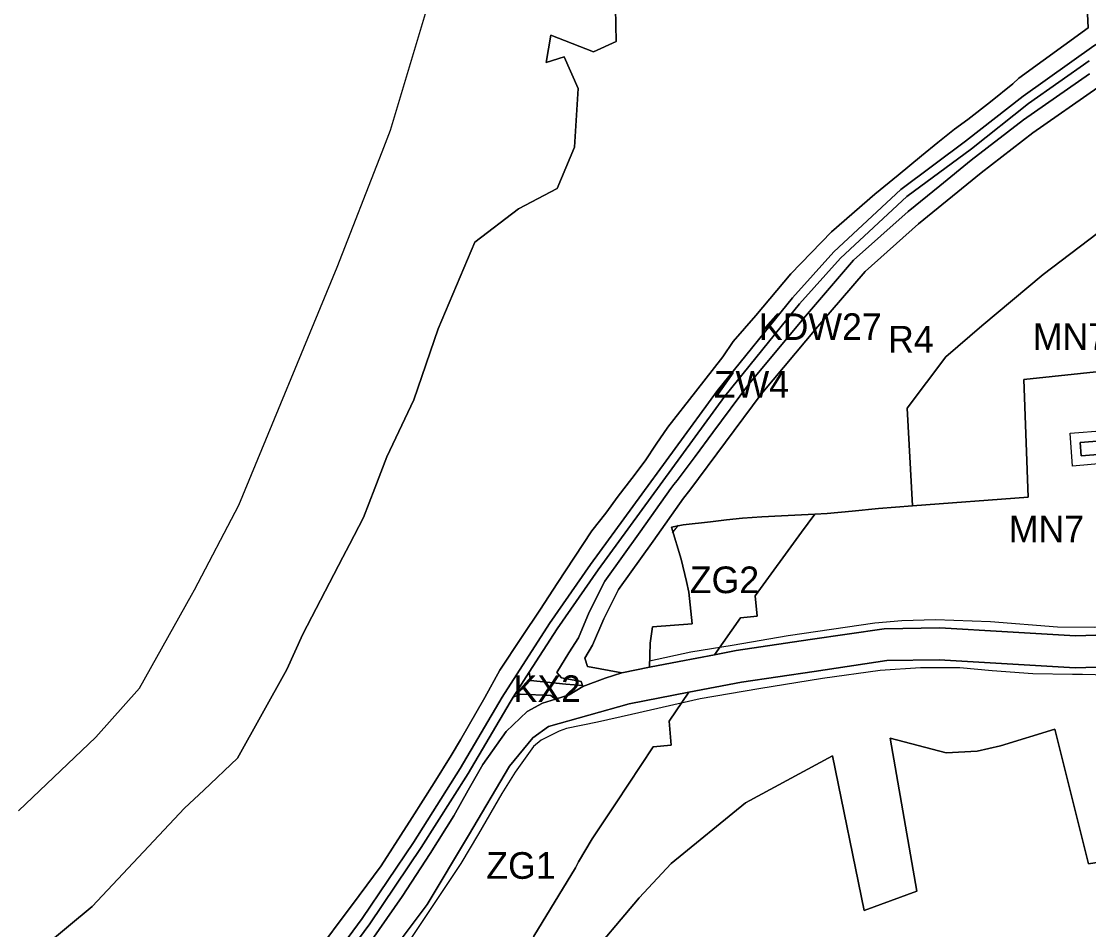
# Model space of a CAD drawing. Extents: x 7428841 to 7433518, y 5545054 to 5546840.
# Drawn here: x 7429514.3 to 7429914.7, y 5545904.8 to 5546245.5 of the extents above; entities that cross this region are included whole.
import ezdxf

# ---------------------------------------------------------------- set-up
doc = ezdxf.new("R2010")
doc.units = 0
for name, color, linetype in [('linie_rozgraniczajace', 7, 'Continuous'), ('linie_zabudowy_nieprzekraczalne', 7, 'Continuous'), ('oznaczenia_przeznaczen', 7, 'Continuous')]:
    doc.layers.add(name, color=color, linetype=linetype)

msp = doc.modelspace()

# ---------------------------------------------------------------- linework, layer by layer
at = {"layer": 'linie_rozgraniczajace'}
for points in [[(7429513.33, 5545949.4), (7429542.31, 5545977.07), (7429558.66, 5545995.42), (7429578.18, 5546030.27), (7429579.34, 5546032.34), (7429595.91, 5546064.01), (7429632.76, 5546153.34), (7429649.66, 5546196.59), (7429652.83, 5546204.72), (7429678.26, 5546289.88)], [(7429494.94, 5545875.35), (7429540.93, 5545913.47), (7429575.57, 5545950.34), (7429582.78, 5545957.17), (7429595.45, 5545969.17), (7429613.89, 5546002.42), (7429619.94, 5546015.65), (7429634.97, 5546044.55), (7429637.46, 5546049.29), (7429642.73, 5546059.36), (7429646.95, 5546070.45), (7429651.47, 5546082.12), (7429661.52, 5546103.6), (7429670.63, 5546130.19), (7429684.39, 5546162.65), (7429700.82, 5546175.18), (7429715.28, 5546182.82), (7429721.78, 5546198.31), (7429723.19, 5546220.36), (7429717.88, 5546232.28), (7429711.15, 5546230.08), (7429712.03, 5546235.21), (7429712.91, 5546240.33), (7429728.93, 5546234.09), (7429737.38, 5546237.96), (7429737.15, 5546250.49)], [(7429737.15, 5546250.49), (7429737.38, 5546237.96), (7429728.93, 5546234.09), (7429712.91, 5546240.33), (7429712.03, 5546235.21), (7429711.15, 5546230.08), (7429717.88, 5546232.28), (7429723.19, 5546220.36), (7429721.78, 5546198.31), (7429715.28, 5546182.82), (7429700.82, 5546175.18), (7429684.39, 5546162.65), (7429670.63, 5546130.19), (7429661.52, 5546103.6), (7429651.47, 5546082.12), (7429646.95, 5546070.45), (7429642.73, 5546059.36), (7429637.46, 5546049.29), (7429634.97, 5546044.55), (7429619.94, 5546015.65), (7429613.89, 5546002.42), (7429595.45, 5545969.17), (7429582.78, 5545957.17), (7429575.57, 5545950.34), (7429540.93, 5545913.47), (7429494.94, 5545875.35)], [(7429932.61, 5546245.81), (7429916.65, 5546236.37), (7429890.04, 5546217.47), (7429868.53, 5546200.53), (7429844.24, 5546182.48), (7429819.06, 5546159.11), (7429803.55, 5546141.79), (7429775.47, 5546107.09), (7429727.84, 5546041.79), (7429712.38, 5546019.62), (7429694.69, 5545991.97), (7429678.9, 5545965.27), (7429661.41, 5545937.52), (7429642.2, 5545909.04), (7429627.76, 5545889.55), (7429578.46, 5545830.77), (7429550.53, 5545801.9), (7429533.05, 5545787.63), (7429518.17, 5545776.56), (7429482.58, 5545755.61)], [(7429482.58, 5545755.61), (7429518.17, 5545776.56), (7429533.05, 5545787.63), (7429550.53, 5545801.9), (7429578.46, 5545830.77), (7429627.76, 5545889.55), (7429642.2, 5545909.04), (7429661.41, 5545937.52), (7429678.9, 5545965.27), (7429694.69, 5545991.97), (7429712.38, 5546019.62), (7429727.84, 5546041.79), (7429775.47, 5546107.09), (7429803.55, 5546141.79), (7429819.06, 5546159.11), (7429844.24, 5546182.48), (7429868.53, 5546200.53), (7429890.04, 5546217.47), (7429916.65, 5546236.37), (7429932.61, 5546245.81)], [(7429914.25, 5546248.32), (7429914.51, 5546243.05), (7429888.46, 5546224.27), (7429886.2, 5546222.04), (7429877.8, 5546215.39), (7429869.4, 5546208.73), (7429864.29, 5546205.05), (7429858.1, 5546200.06), (7429851.91, 5546195.07), (7429843.21, 5546187.87), (7429834.5, 5546180.68), (7429818.21, 5546166.64), (7429810.61, 5546158.76), (7429803.01, 5546150.88), (7429789.8, 5546135.16), (7429781.33, 5546125.42), (7429777.4, 5546119.65), (7429767.23, 5546106.62), (7429756.78, 5546093.36), (7429752.4, 5546086.89), (7429748.3, 5546080.67), (7429743.26, 5546074.03), (7429738.23, 5546067.39), (7429733.59, 5546061.07), (7429728.34, 5546054.38), (7429715.29, 5546034.7), (7429709, 5546025.01), (7429701.98, 5546014.44), (7429693.81, 5546002.15), (7429688.22, 5545991.91), (7429679.11, 5545976.01), (7429675.56, 5545970.15), (7429669.22, 5545959.93), (7429660.9, 5545946.85), (7429649.35, 5545928.71), (7429641.03, 5545917.61), (7429621.41, 5545891.37)], [(7429715.29, 5546034.7), (7429728.34, 5546054.38), (7429733.59, 5546061.07), (7429738.23, 5546067.39), (7429743.26, 5546074.03), (7429748.3, 5546080.67), (7429752.4, 5546086.89), (7429756.78, 5546093.36), (7429767.23, 5546106.62), (7429777.4, 5546119.65), (7429781.33, 5546125.42), (7429789.8, 5546135.16), (7429803.01, 5546150.88), (7429810.61, 5546158.76), (7429818.21, 5546166.64), (7429834.5, 5546180.68), (7429843.21, 5546187.87), (7429851.91, 5546195.07), (7429858.1, 5546200.06), (7429864.29, 5546205.05), (7429869.4, 5546208.73), (7429877.8, 5546215.39), (7429886.2, 5546222.04), (7429888.46, 5546224.27), (7429914.51, 5546243.05), (7429914.25, 5546248.32)], [(7429914.81, 5546230.77), (7429892.14, 5546214.67), (7429870.66, 5546197.75), (7429846.48, 5546179.78), (7429821.56, 5546156.65), (7429806.22, 5546139.52), (7429778.24, 5546104.95), (7429730.69, 5546039.75), (7429715.29, 5546017.67), (7429704.85, 5546001.35), (7429698.85, 5545991.98), (7429697.67, 5545990.14), (7429681.88, 5545963.44), (7429664.34, 5545935.61), (7429645.05, 5545907.02), (7429630.51, 5545887.39), (7429581.07, 5545828.42), (7429552.9, 5545799.32), (7429535.21, 5545784.87), (7429520.11, 5545773.64), (7429483.94, 5545752.35)], [(7429914.96, 5546225.81), (7429890.23, 5546208.55), (7429870.62, 5546193.44), (7429858.8, 5546183.83), (7429846.97, 5546174.21), (7429836.74, 5546165.06), (7429826.51, 5546155.91), (7429808.48, 5546134.89), (7429787.08, 5546109.35), (7429773.71, 5546091.34), (7429767.02, 5546082.33), (7429760.33, 5546073.32), (7429759.73, 5546072.55), (7429759.13, 5546071.78), (7429757.93, 5546070.24), (7429746.45, 5546054.05), (7429733.18, 5546035.56), (7429727.36, 5546023.86), (7429723.28, 5546014.3), (7429719.75, 5546008.65), (7429715.18, 5546001.33), (7429716.92, 5545999.23), (7429724.33, 5545997.88), (7429724.81, 5545996.46), (7429718.52, 5545996.88), (7429705.34, 5545998.32), (7429704.85, 5546001.35), (7429715.29, 5546017.67), (7429730.69, 5546039.75), (7429778.24, 5546104.95), (7429806.22, 5546139.52), (7429821.56, 5546156.65), (7429846.48, 5546179.78), (7429870.66, 5546197.75), (7429892.14, 5546214.67), (7429914.81, 5546230.77)], [(7429918.09, 5546220.68), (7429893.78, 5546203.71), (7429874.35, 5546188.74), (7429850.86, 5546169.64), (7429830.81, 5546151.7), (7429813.06, 5546131.01), (7429791.79, 5546105.63), (7429765.11, 5546069.68), (7429762.74, 5546066.66), (7429751.34, 5546050.57), (7429738.34, 5546032.45), (7429732.81, 5546021.35), (7429728.62, 5546011.52), (7429725.74, 5546006.69), (7429726.63, 5546003.55), (7429739.62, 5546001.21), (7429733.34, 5545999.19), (7429724.97, 5545995.99), (7429724.81, 5545996.46), (7429724.33, 5545997.88), (7429716.92, 5545999.23), (7429715.18, 5546001.33), (7429719.75, 5546008.65), (7429723.28, 5546014.3), (7429727.36, 5546023.86), (7429733.18, 5546035.56), (7429746.45, 5546054.05), (7429757.93, 5546070.24), (7429759.13, 5546071.78), (7429759.73, 5546072.55), (7429760.33, 5546073.32), (7429767.02, 5546082.33), (7429773.71, 5546091.34), (7429787.08, 5546109.35), (7429808.48, 5546134.89), (7429826.51, 5546155.91), (7429836.74, 5546165.06), (7429846.97, 5546174.21), (7429858.8, 5546183.83), (7429870.62, 5546193.44), (7429890.23, 5546208.55), (7429914.96, 5546225.81)], [(7429921.51, 5546168.74), (7429897.65, 5546150.58), (7429874.63, 5546131.35), (7429861.13, 5546119.63), (7429846.54, 5546100.39), (7429848.58, 5546063.8), (7429835.87, 5546062.81), (7429825.94, 5546061.84), (7429816.58, 5546060.98), (7429811.98, 5546060.73), (7429799.47, 5546060.06), (7429792.14, 5546059.62), (7429784.81, 5546059.18), (7429778.8, 5546058.5), (7429772.78, 5546057.81), (7429762.54, 5546056.67), (7429758.22, 5546055.81), (7429761.79, 5546043.84), (7429763.81, 5546035.38), (7429764.75, 5546031.46), (7429765.9, 5546019.47), (7429751.03, 5546018.35), (7429750.24, 5546012.33), (7429749.98, 5546003.22), (7429739.62, 5546001.21), (7429726.63, 5546003.55), (7429725.74, 5546006.69), (7429728.62, 5546011.52), (7429732.81, 5546021.35), (7429738.34, 5546032.45), (7429751.34, 5546050.57), (7429762.74, 5546066.66), (7429765.11, 5546069.68), (7429791.79, 5546105.63), (7429813.06, 5546131.01), (7429830.81, 5546151.7), (7429850.86, 5546169.64), (7429874.35, 5546188.74), (7429893.78, 5546203.71), (7429918.09, 5546220.68)], [(7429921.21, 5546015.41), (7429909.72, 5546015.03), (7429884.28, 5546016.52), (7429858.83, 5546018.02), (7429837.95, 5546017.71), (7429810.22, 5546013.62), (7429782.49, 5546009.52), (7429774.31, 5546007.94), (7429784.04, 5546021.81), (7429790.39, 5546022.37), (7429789.62, 5546030.07), (7429807.01, 5546053.91), (7429811.98, 5546060.73), (7429816.58, 5546060.98), (7429825.94, 5546061.84), (7429835.87, 5546062.81), (7429848.58, 5546063.8), (7429891.95, 5546067.04), (7429890.36, 5546111.21), (7429922.25, 5546114.62)], [(7429927.26, 5546088.81), (7429911.47, 5546087.59), (7429911.85, 5546082.6), (7429943.48, 5546085.05)], [(7429514.31, 5545783.59), (7429515.27, 5545781.89), (7429545.46, 5545804.09), (7429559.76, 5545819.83), (7429572.5, 5545833.72), (7429579.76, 5545842.36), (7429585.45, 5545849.15), (7429591.17, 5545856.04), (7429600.14, 5545866.56), (7429613.69, 5545882.38), (7429621.41, 5545891.37), (7429641.03, 5545917.61), (7429649.35, 5545928.71), (7429660.9, 5545946.85), (7429669.22, 5545959.93), (7429675.56, 5545970.15), (7429679.11, 5545976.01), (7429688.22, 5545991.91), (7429693.81, 5546002.15), (7429701.98, 5546014.44), (7429709, 5546025.01), (7429715.29, 5546034.7)], [(7429639.95, 5545892.51), (7429657.22, 5545917.24), (7429667.73, 5545933.39), (7429676.54, 5545947.49), (7429681.99, 5545957.1), (7429687.44, 5545966.71), (7429696.16, 5545979.1), (7429704.07, 5545986.59), (7429709.75, 5545989.74), (7429714.67, 5545991.26), (7429719.79, 5545992.85), (7429724.97, 5545995.99), (7429733.34, 5545999.19), (7429739.62, 5546001.21), (7429749.98, 5546003.22), (7429761.06, 5546005.37), (7429774.31, 5546007.94), (7429782.49, 5546009.52), (7429810.22, 5546013.62), (7429837.95, 5546017.71), (7429858.83, 5546018.02), (7429884.28, 5546016.52), (7429909.72, 5546015.03), (7429921.21, 5546015.41)], [(7429921.65, 5546003.42), (7429909.57, 5546003.02), (7429884.07, 5546004.52), (7429858.57, 5546006.01), (7429838.92, 5546005.72), (7429811.72, 5546001.71), (7429784.51, 5545997.69), (7429764.65, 5545993.84), (7429742.37, 5545989.53), (7429727.19, 5545985.3), (7429712, 5545981.08), (7429706.14, 5545976.78), (7429697.48, 5545966.08), (7429682.05, 5545940.18), (7429666.61, 5545914.27), (7429649.27, 5545891.27)], [(7429706.56, 5545902.43), (7429722.17, 5545928), (7429723.32, 5545930.25), (7429728.4, 5545938.93), (7429737.44, 5545952.4), (7429751.29, 5545973.39), (7429758.12, 5545974.05), (7429757.26, 5545982.98), (7429764.65, 5545993.84), (7429784.51, 5545997.69), (7429811.72, 5546001.71), (7429838.92, 5546005.72), (7429858.57, 5546006.01), (7429884.07, 5546004.52), (7429909.57, 5546003.02), (7429921.65, 5546003.42)], [(7429630.51, 5545887.39), (7429645.05, 5545907.02), (7429664.34, 5545935.61), (7429681.88, 5545963.44), (7429697.67, 5545990.14), (7429698.85, 5545991.98), (7429701.57, 5545993.09), (7429712.88, 5545992.64), (7429714.67, 5545991.26), (7429709.75, 5545989.74), (7429704.07, 5545986.59), (7429696.16, 5545979.1), (7429687.44, 5545966.71), (7429681.99, 5545957.1), (7429676.54, 5545947.49), (7429667.73, 5545933.39), (7429657.22, 5545917.24), (7429639.95, 5545892.51)], [(7430003.99, 5545943.38), (7429914.54, 5545929.5), (7429901.95, 5545979.97), (7429881.59, 5545973.77), (7429872.82, 5545971.77), (7429861.25, 5545971.2), (7429840.25, 5545976.65), (7429850.22, 5545919.26), (7429830.42, 5545912.04), (7429818.63, 5545969.99), (7429785.95, 5545952.41), (7429758.01, 5545929.66), (7429746.06, 5545916.73), (7429704.27, 5545867.25)], [(7429704.27, 5545867.25), (7429746.06, 5545916.73), (7429758.01, 5545929.66), (7429785.95, 5545952.41), (7429818.63, 5545969.99), (7429830.42, 5545912.04), (7429850.22, 5545919.26), (7429840.25, 5545976.65), (7429861.25, 5545971.2), (7429872.82, 5545971.77), (7429881.59, 5545973.77), (7429901.95, 5545979.97), (7429914.54, 5545929.5), (7430003.99, 5545943.38)]]:
    msp.add_lwpolyline(points, dxfattribs=at)
for points in [[(7429846.54, 5546100.39), (7429861.13, 5546119.63), (7429874.63, 5546131.35), (7429897.65, 5546150.58), (7429921.51, 5546168.74), (7429941.44, 5546181.94), (7429961.76, 5546194.72), (7429963.82, 5546189.06), (7429964.54, 5546184.93), (7429966.59, 5546175.7), (7429970.01, 5546151.12), (7429970.86, 5546136.41), (7429970.85, 5546128.34), (7429970.09, 5546119.91), (7429944.64, 5546116.84), (7429922.25, 5546114.62), (7429890.36, 5546111.21), (7429891.95, 5546067.04), (7429848.58, 5546063.8)], [(7429911.47, 5546087.59), (7429927.26, 5546088.81), (7429946.61, 5546090.36), (7429951.14, 5546090.8), (7429956.17, 5546091.27), (7429960.81, 5546091.85), (7429968.11, 5546098.66), (7429967.24, 5546089.28), (7429967.53, 5546082.3), (7429961.7, 5546086.64), (7429950.06, 5546085.67), (7429943.48, 5546085.05), (7429911.85, 5546082.6)], [(7429749.98, 5546003.22), (7429750.24, 5546012.33), (7429751.03, 5546018.35), (7429765.9, 5546019.47), (7429764.75, 5546031.46), (7429763.81, 5546035.38), (7429761.79, 5546043.84), (7429758.22, 5546055.81), (7429762.54, 5546056.67), (7429772.78, 5546057.81), (7429778.8, 5546058.5), (7429784.81, 5546059.18), (7429792.14, 5546059.62), (7429799.47, 5546060.06), (7429811.98, 5546060.73), (7429807.01, 5546053.91), (7429789.62, 5546030.07), (7429790.39, 5546022.37), (7429784.04, 5546021.81), (7429774.31, 5546007.94), (7429761.06, 5546005.37)], [(7429698.85, 5545991.98), (7429704.85, 5546001.35), (7429705.34, 5545998.32), (7429718.52, 5545996.88), (7429724.81, 5545996.46), (7429724.97, 5545995.99), (7429719.79, 5545992.85), (7429714.67, 5545991.26), (7429712.88, 5545992.64), (7429701.57, 5545993.09)], [(7429641.81, 5545881.38), (7429649.27, 5545891.27), (7429666.61, 5545914.27), (7429682.05, 5545940.18), (7429697.48, 5545966.08), (7429706.14, 5545976.78), (7429712, 5545981.08), (7429727.19, 5545985.3), (7429742.37, 5545989.53), (7429764.65, 5545993.84), (7429757.26, 5545982.98), (7429758.12, 5545974.05), (7429751.29, 5545973.39), (7429737.44, 5545952.4), (7429728.4, 5545938.93), (7429723.32, 5545930.25), (7429722.17, 5545928), (7429706.56, 5545902.43), (7429698.36, 5545890.17), (7429691.06, 5545879.77), (7429681.06, 5545865.42), (7429677.35, 5545860.63), (7429651.64, 5545875.64)]]:
    msp.add_lwpolyline(points, close=True, dxfattribs=at)
at = {"layer": 'linie_zabudowy_nieprzekraczalne'}
for points in [[(7429963.7, 5546080.81), (7429960.45, 5546083.27), (7429908.57, 5546078.73), (7429907.69, 5546091.05), (7429959.24, 5546095.05), (7429965.49, 5546100.05)], [(7429760.64, 5546056.58), (7429758.5, 5546053.7)], [(7429749.93, 5546005.61), (7429765.5, 5546009), (7429780.94, 5546011.51), (7429801.93, 5546015.2), (7429818.17, 5546017.53), (7429834.41, 5546019.85), (7429844.59, 5546020.77), (7429857.23, 5546021.19), (7429877.88, 5546020.42), (7429902.96, 5546018.42), (7429917.04, 5546018.26), (7429930.64, 5546018.81), (7429940.01, 5546020.35), (7429947.23, 5546023.49), (7429957.72, 5546029.59), (7429968.03, 5546035.92), (7429980.3, 5546042.36)], [(7429921.82, 5546000.3), (7429912.29, 5546000.5), (7429908.61, 5546000.54), (7429893.67, 5546000.81), (7429878.41, 5546001.93), (7429866.38, 5546002.98), (7429851.57, 5546002.98), (7429836.49, 5546001.97), (7429814.84, 5545999.05), (7429790.96, 5545995.18), (7429768.98, 5545991.34), (7429743.15, 5545985.55), (7429730.5, 5545982.66), (7429718.78, 5545980.26), (7429716.04, 5545979.3), (7429709.34, 5545975.88), (7429706.42, 5545973.47), (7429699.56, 5545963.84), (7429694.52, 5545955.91), (7429685.84, 5545940.72), (7429679.16, 5545929.64), (7429667.49, 5545911.95), (7429658.45, 5545898.47)]]:
    msp.add_lwpolyline(points, dxfattribs=at)

# ---------------------------------------------------------------- texts
at = {"layer": 'oznaczenia_przeznaczen'}
for s, p in [('KDW27', (7429790.97, 5546126.01)), ('R4', (7429839.44, 5546121.3)), ('MN72', (7429893.7, 5546122.31)), ('ZW4', (7429774.05, 5546104.35)), ('MN7', (7429884.73, 5546050.11)), ('ZG2', (7429765.06, 5546031.04)), ('KX2', (7429698.96, 5545990.2)), ('ZG1', (7429688.73, 5545923.88))]:
    msp.add_text(s, height=10, dxfattribs=at).set_placement(p)

doc.saveas('drawing.dxf')
